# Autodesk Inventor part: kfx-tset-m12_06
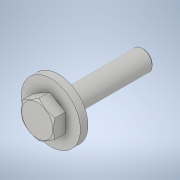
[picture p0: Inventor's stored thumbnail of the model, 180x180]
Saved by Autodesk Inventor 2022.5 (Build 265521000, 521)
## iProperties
Created: 2021-10
Part Number: kfx-tset-m12_06
Material: 一般
Document SubType Name: Modeling
Designer: ImaoCorp
Density: 1 g/cm^3
Appearance: 既定
Author: ImaoCorp
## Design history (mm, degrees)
feature "kfx-tset-m12_06"
node "ソリッド1"
